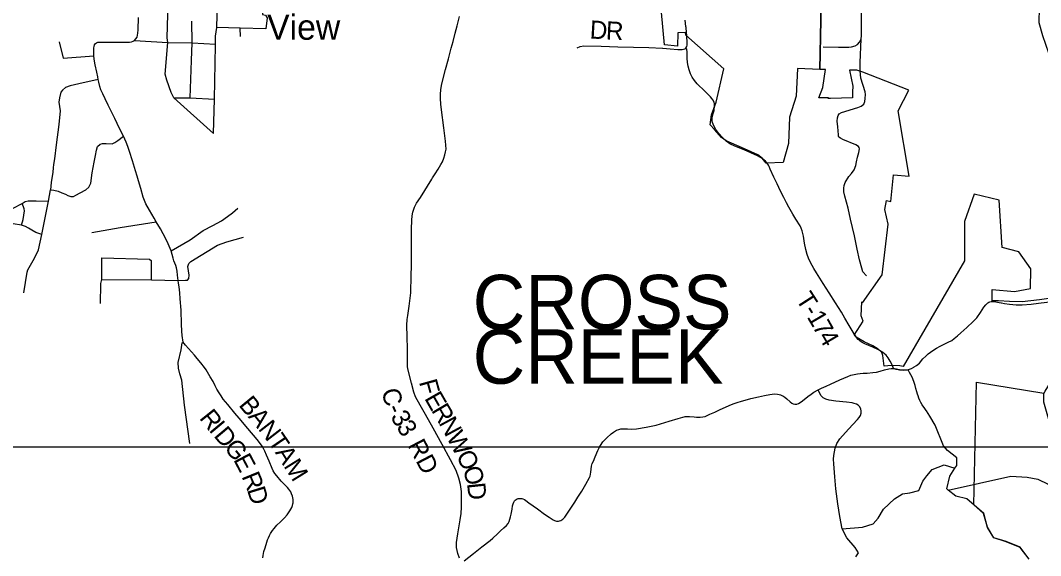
# Model space of a CAD drawing. Extents: x 2402298 to 2498138, y 789485 to 950881.
# Drawn here: x 2459820 to 2476688, y 857480 to 866330 of the extents above; entities that cross this region are included whole.
import ezdxf

# ---------------------------------------------------------------- set-up
doc = ezdxf.new("R2010")
doc.units = 0
for name, color, linetype in [('GM_X_City_Street', 7, 'Continuous'), ('GM_X_Corporation', 7, 'Continuous'), ('GM_X_County_Road', 7, 'Continuous'), ('GM_X_County_Road_Text', 7, 'Continuous'), ('GM_X_Township_Road', 7, 'Continuous'), ('GM_X_Township_Road_Text', 7, 'Continuous'), ('GM_X_Township_Text', 7, 'Continuous'), ('GM_X_Unincorporated_Text', 7, 'Continuous'), ('SH_Text', 7, 'Continuous')]:
    doc.layers.add(name, color=color, linetype=linetype)

msp = doc.modelspace()

# ---------------------------------------------------------------- linework, layer by layer
at = {"layer": 'GM_X_City_Street'}
for points in [[(2473702, 865498), (2473705, 865633), (2473721, 866022), (2473726, 866080), (2473726, 866229), (2473724, 866463), (2473740, 866706), (2473741, 867188), (2473738, 867463), (2473727, 867640), (2473709, 867893), (2473702, 868056), (2473707, 868123), (2473735, 868179), (2473826, 868276), (2473925, 868383), (2474020, 868468), (2474080, 868533), (2474140, 868623), (2474175, 868694), (2474179, 868741), (2474173, 868786)], [(2473095, 865892), (2473349, 865889), (2473471, 865889), (2473520, 865890), (2473560, 865893), (2473623, 865907), (2473663, 865933), (2473691, 865972), (2473721, 866022)]]:
    msp.add_lwpolyline(points, dxfattribs=at)
at = {"layer": 'GM_X_Corporation'}
for points in [[(2473072, 867154), (2473036, 865518), (2472666, 865532), (2472649, 865076), (2472537, 864730), (2472521, 864292), (2472432, 863982), (2472150, 863967), (2472082, 864052), (2472012, 864105), (2471791, 864204), (2471487, 864337), (2471411, 864393), (2471296, 864526), (2471227, 864604), (2471249, 864769), (2471324, 864976), (2471453, 865528), (2470820, 866084), (2470816, 866131), (2470688, 866127), (2470683, 865903), (2470469, 865924), (2470347, 867239)], [(2476971, 861751), (2476668, 861707), (2476385, 861674), (2476175, 861679), (2475993, 861691), (2475889, 861694), (2475889, 861880), (2476256, 861847), (2476522, 861894), (2476528, 862221), (2476330, 862503), (2476052, 862577), (2476001, 863360), (2475589, 863458), (2475428, 863007), (2475428, 862353), (2474418, 860606), (2474359, 860616), (2474225, 860626), (2474100, 860611), (2474080, 860789), (2474061, 860839), (2474005, 860896), (2473915, 860948), (2473772, 861012), (2473703, 861053), (2473638, 861093), (2473606, 861123), (2473752, 861355), (2473722, 861442), (2473730, 861675), (2473743, 861660), (2474066, 862121), (2474170, 862961), (2474115, 863202), (2474139, 863354), (2474209, 863335), (2474258, 863778), (2474515, 863754), (2474332, 864833), (2474512, 865176), (2473748, 865476), (2473652, 865506), (2473531, 865509), (2473582, 865244), (2473576, 865150), (2473579, 865051), (2473214, 865039), (2473198, 865038), (2473175, 865039), (2473179, 865047), (2473022, 865050), (2473090, 865218), (2473129, 865517), (2473036, 865518), (2473072, 867154)], [(2476498, 857423), (2476351, 857617), (2476118, 857713), (2475913, 857775), (2475808, 857950), (2475746, 858177), (2475586, 858319), (2475627, 860345), (2476742, 860163)]]:
    msp.add_lwpolyline(points, dxfattribs=at)
at = {"layer": 'GM_X_County_Road'}
for p, q in [((2474258, 860572), (2474294, 860564)), ((2474294, 860564), (2474303, 860563)), ((2474590, 860597), (2474595, 860600))]:
    msp.add_line(p, q, dxfattribs=at)
for points in [[(2476824, 865786), (2476725, 866075), (2476667, 866287), (2476667, 866397), (2476673, 866484), (2476673, 866612), (2476679, 866737), (2476675, 866808), (2476651, 866875), (2476580, 867029), (2476573, 867046)], [(2462429, 862029), (2462420, 862118), (2462411, 862185), (2462400, 862237), (2462388, 862279), (2462358, 862356), (2462345, 862399), (2462313, 862522), (2462265, 862635), (2462219, 862731), (2462182, 862799), (2462135, 862884), (2462067, 863000), (2462034, 863058), (2461955, 863193), (2461895, 863299), (2461852, 863407), (2461810, 863549), (2461771, 863678), (2461748, 863755), (2461722, 863845), (2461672, 864009), (2461625, 864160), (2461598, 864246), (2461571, 864315), (2461524, 864415), (2461461, 864544), (2461379, 864710), (2461332, 864808), (2461273, 864928), (2461221, 865032), (2461181, 865113), (2461152, 865182), (2461134, 865237), (2461118, 865306), (2461107, 865354), (2461101, 865399), (2461084, 865475), (2461058, 865593), (2461046, 865655), (2461039, 865697), (2461034, 865744), (2461033, 865844), (2461033, 865874), (2461038, 865899), (2461046, 865926), (2461062, 865948), (2461080, 865960), (2461099, 865969), (2461255, 865970), (2461459, 865968), (2461591, 865969), (2461626, 865971), (2461655, 865976), (2461684, 865987), (2461706, 866000), (2461730, 866025), (2461748, 866054), (2461756, 866084), (2461761, 866118), (2461766, 866175), (2461773, 866376)], [(2466634, 863724), (2466678, 863795), (2466725, 863869), (2466772, 863947), (2466797, 863993), (2466821, 864050), (2466838, 864105), (2466850, 864156), (2466857, 864202), (2466855, 864265), (2466846, 864334), (2466820, 864553), (2466783, 864853), (2466771, 864946), (2466765, 865036), (2466765, 865106), (2466773, 865187), (2466788, 865279), (2466851, 865519), (2466898, 865696), (2466943, 865870), (2466973, 865981), (2467010, 866120), (2467041, 866241), (2467082, 866396)], [(2467082, 857435), (2467055, 857512), (2467032, 857612), (2467032, 857694), (2467052, 857842), (2467093, 858071), (2467105, 858174), (2467115, 858279), (2467115, 858413), (2467111, 858540), (2467099, 858653), (2467070, 858762), (2467027, 858886), (2466932, 859063), (2466792, 859319), (2466645, 859589), (2466518, 859811), (2466429, 859966), (2466353, 860103), (2466327, 860183), (2466286, 860331), (2466225, 860569), (2466218, 860608), (2466219, 860668), (2466220, 860900), (2466216, 861095), (2466211, 861291), (2466215, 861382), (2466225, 861450), (2466247, 861606), (2466275, 861825), (2466281, 862114), (2466284, 862274), (2466287, 862582), (2466287, 862759), (2466288, 862876), (2466294, 863026), (2466296, 863098), (2466307, 863159), (2466335, 863244), (2466369, 863307), (2466435, 863404), (2466620, 863702), (2466634, 863724)], [(2462510, 861010), (2462492, 861119), (2462488, 861189), (2462484, 861306), (2462477, 861538), (2462464, 861725), (2462455, 861823), (2462443, 861925), (2462435, 861986), (2462429, 862029)], [(2474595, 860600), (2474634, 860623), (2474684, 860664), (2474743, 860733), (2474788, 860780), (2474830, 860817), (2474908, 860873), (2474966, 860911), (2475026, 860945), (2475157, 861007), (2475218, 861039), (2475261, 861068), (2475315, 861113), (2475368, 861162), (2475469, 861253), (2475575, 861349), (2475635, 861414), (2475695, 861498), (2475749, 861586), (2475782, 861628), (2475813, 861658), (2475833, 861671), (2475851, 861678), (2475873, 861682), (2475893, 861683), (2475947, 861677), (2476002, 861666), (2476034, 861660)], [(2476034, 861660), (2476039, 861659), (2476091, 861649), (2476176, 861635), (2476282, 861626), (2476385, 861627), (2476532, 861639), (2476654, 861653), (2476980, 861692), (2477200, 861722), (2477262, 861726), (2477340, 861721), (2477430, 861709), (2477490, 861700), (2477564, 861687), (2477643, 861674), (2477697, 861665), (2477741, 861661), (2477777, 861662), (2477812, 861676), (2477843, 861697), (2477870, 861719), (2477894, 861754), (2477905, 861772)], [(2463829, 857444), (2463832, 857482), (2463847, 857548), (2463866, 857609), (2463895, 857703), (2463908, 857739), (2463921, 857773), (2463938, 857812), (2463957, 857846), (2463988, 857894), (2464015, 857930), (2464062, 857982), (2464121, 858039), (2464156, 858072), (2464186, 858105), (2464228, 858154), (2464275, 858220), (2464305, 858277), (2464317, 858308), (2464324, 858335), (2464327, 858355), (2464328, 858378), (2464327, 858406), (2464324, 858435), (2464319, 858460), (2464304, 858502), (2464289, 858533), (2464258, 858578), (2464236, 858605), (2464218, 858625), (2464134, 858712), (2464058, 858796), (2464026, 858838), (2463999, 858882), (2463981, 858922), (2463932, 859040), (2463890, 859142), (2463861, 859206), (2463838, 859252), (2463816, 859290), (2463773, 859351), (2463736, 859397), (2463578, 859582), (2463435, 859752), (2463364, 859835), (2463247, 859978), (2463175, 860066), (2463137, 860120), (2463104, 860172), (2463070, 860230), (2463041, 860286), (2463005, 860357), (2462959, 860437), (2462890, 860551), (2462863, 860589), (2462804, 860666), (2462745, 860737), (2462697, 860793), (2462598, 860904), (2462552, 860957), (2462529, 860985), (2462510, 861010)], [(2473009, 860221), (2473063, 860246), (2473142, 860283), (2473216, 860317), (2473370, 860388), (2473503, 860443), (2473552, 860461), (2473603, 860476), (2473662, 860487), (2473706, 860493), (2473755, 860496), (2473822, 860499), (2473915, 860507), (2473977, 860514), (2474034, 860529), (2474109, 860554), (2474178, 860569), (2474216, 860573), (2474258, 860572)], [(2474303, 860563), (2474356, 860553), (2474426, 860547), (2474496, 860553)], [(2474496, 860553), (2474502, 860555), (2474555, 860576), (2474590, 860597)], [(2467156, 857392), (2467310, 857512), (2467451, 857623), (2467585, 857728), (2467632, 857770), (2467706, 857842), (2467759, 857892), (2467815, 857938), (2467856, 857978), (2467883, 858011), (2467899, 858042), (2467914, 858082), (2467925, 858120), (2467936, 858166), (2467948, 858247), (2467957, 858301), (2467965, 858337), (2467977, 858363), (2467991, 858383), (2468003, 858396), (2468017, 858407), (2468032, 858416), (2468051, 858423), (2468071, 858426), (2468091, 858426), (2468109, 858423), (2468128, 858417), (2468153, 858405), (2468176, 858391), (2468227, 858355), (2468367, 858254), (2468487, 858167), (2468560, 858114), (2468594, 858091), (2468631, 858070), (2468650, 858061), (2468668, 858055), (2468685, 858051), (2468701, 858050), (2468718, 858051), (2468734, 858053), (2468756, 858061), (2468773, 858070), (2468789, 858082), (2468804, 858096), (2468822, 858118), (2468845, 858149), (2468986, 858364), (2469038, 858444), (2469102, 858547), (2469168, 858661), (2469229, 858769), (2469238, 858795), (2469245, 858824), (2469250, 858858), (2469264, 858956), (2469276, 859001), (2469293, 859041), (2469325, 859114), (2469368, 859219), (2469393, 859271), (2469409, 859298), (2469450, 859359), (2469514, 859427), (2469586, 859491), (2469626, 859522), (2469678, 859553), (2469713, 859566), (2469750, 859574), (2469805, 859576), (2469858, 859575), (2469926, 859573), (2470007, 859576), (2470168, 859604), (2470330, 859638), (2470544, 859704), (2470695, 859748), (2470770, 859771), (2470793, 859776), (2470813, 859778), (2470845, 859781), (2470881, 859781), (2470959, 859776), (2470997, 859770), (2471058, 859767), (2471105, 859773), (2471140, 859782), (2471219, 859816), (2471303, 859854), (2471390, 859893), (2471478, 859933), (2471541, 859960), (2471607, 859988), (2471670, 860010), (2471744, 860033), (2471804, 860051), (2471895, 860075), (2472024, 860106), (2472121, 860129), (2472211, 860146), (2472247, 860150), (2472290, 860152), (2472337, 860150), (2472363, 860145), (2472385, 860137), (2472407, 860129), (2472425, 860120), (2472460, 860099), (2472493, 860071), (2472547, 860020), (2472573, 860002), (2472596, 859989), (2472625, 859984), (2472655, 859985), (2472684, 859994), (2472728, 860020), (2472779, 860059), (2472840, 860109), (2472895, 860151), (2472938, 860180), (2473009, 860221)]]:
    msp.add_lwpolyline(points, dxfattribs=at)
at = {"layer": 'GM_X_Township_Road'}
for p, q in [((2463459, 866061), (2463453, 866203)), ((2470823, 866231), (2470813, 866334)), ((2461987, 862040), (2461989, 862355)), ((2461145, 861651), (2461150, 861968)), ((2474294, 860564), (2474258, 860572)), ((2474303, 860563), (2474294, 860564))]:
    msp.add_line(p, q, dxfattribs=at)
for points in [[(2463012, 864460), (2462355, 865050), (2462314, 865137), (2462240, 865342), (2462213, 865439), (2462256, 865962), (2462247, 866044), (2462269, 866822), (2462211, 866834), (2462182, 866861), (2462160, 866898), (2462078, 867286), (2462065, 867390), (2462078, 867545)], [(2463047, 865921), (2463047, 865936), (2463045, 866070), (2463067, 866213), (2463079, 866617), (2463064, 866803)], [(2463079, 866617), (2463789, 866598), (2463816, 866576), (2463822, 866430), (2463873, 866414), (2463898, 866374), (2463879, 866191), (2463453, 866203), (2463067, 866213)], [(2462626, 865048), (2462647, 865668), (2462658, 865959), (2462653, 866320)], [(2470832, 866128), (2470825, 866210), (2470823, 866231)], [(2470843, 865920), (2470846, 865954), (2470836, 866081), (2470832, 866128)], [(2460462, 865978), (2460529, 865706), (2461034, 865744)], [(2461706, 866000), (2462256, 865962), (2462658, 865959), (2463047, 865936)], [(2463012, 864460), (2463030, 865027), (2463047, 865921)], [(2469026, 865874), (2469074, 865897), (2469134, 865907), (2469423, 865902), (2469697, 865891), (2469955, 865888), (2470212, 865880), (2470436, 865870), (2470442, 865870)], [(2470442, 865870), (2470562, 865862), (2470691, 865851), (2470698, 865851)], [(2470698, 865851), (2470764, 865850), (2470805, 865859), (2470822, 865869)], [(2471276, 864789), (2471291, 864839), (2471297, 864918), (2471295, 864949), (2471288, 864979), (2471269, 865016), (2471251, 865041), (2471229, 865064), (2471135, 865157), (2471009, 865281), (2470963, 865335), (2470926, 865392), (2470900, 865449), (2470876, 865511), (2470860, 865572), (2470850, 865636), (2470846, 865704), (2470843, 865802), (2470836, 865854), (2470822, 865869), (2470841, 865900), (2470843, 865920)], [(2461107, 865354), (2460784, 865280), (2460640, 865246), (2460567, 865219), (2460514, 865175), (2460488, 865141), (2460465, 865052), (2460457, 864979), (2460475, 864833), (2460455, 864606), (2460410, 864271), (2460384, 864039), (2460369, 863945), (2460363, 863892)], [(2473808, 862106), (2473750, 862171), (2473730, 862231), (2473693, 862368), (2473657, 862546), (2473610, 862769), (2473544, 863043), (2473504, 863224), (2473451, 863422), (2473435, 863493), (2473432, 863556), (2473439, 863600), (2473454, 863652), (2473517, 863747), (2473561, 863799), (2473603, 863860), (2473632, 863932), (2473646, 863992), (2473663, 864068), (2473681, 864145), (2473692, 864208), (2473690, 864228), (2473679, 864245), (2473634, 864275), (2473418, 864362), (2473378, 864384), (2473354, 864398), (2473348, 864418), (2473347, 864440), (2473333, 864568), (2473327, 864665), (2473330, 864718), (2473340, 864758), (2473355, 864783), (2473394, 864809), (2473668, 864892), (2473720, 864914), (2473764, 864944), (2473782, 864988), (2473788, 865037), (2473791, 865103), (2473785, 865150), (2473716, 865373), (2473702, 865498)], [(2462355, 865050), (2462626, 865048), (2463030, 865027)], [(2472188, 863934), (2472168, 863968), (2472140, 864004), (2472083, 864049), (2472006, 864090), (2471787, 864187), (2471632, 864250), (2471550, 864290), (2471488, 864335), (2471429, 864394), (2471368, 864462), (2471319, 864526), (2471281, 864596), (2471260, 864657), (2471258, 864709), (2471265, 864753), (2471276, 864789)], [(2460363, 863892), (2460355, 863819), (2460329, 863647), (2460320, 863526), (2460370, 863520), (2460442, 863508), (2460506, 863481), (2460567, 863458), (2460603, 863433), (2460651, 863419), (2460695, 863419), (2460739, 863441), (2460807, 863481), (2460899, 863526), (2460953, 863572), (2460986, 863636), (2461005, 863811), (2461041, 863984), (2461059, 864094), (2461078, 864186), (2461095, 864245), (2461137, 864283), (2461178, 864294), (2461240, 864295), (2461339, 864291), (2461382, 864310), (2461430, 864345), (2461524, 864415)], [(2473681, 861048), (2473673, 861055), (2473648, 861082), (2473604, 861148), (2473525, 861282), (2473453, 861408), (2473395, 861503), (2473298, 861661), (2473191, 861824), (2473091, 861980), (2473038, 862068), (2472985, 862153), (2472940, 862228), (2472884, 862324), (2472849, 862397), (2472828, 862458), (2472806, 862541), (2472782, 862646), (2472765, 862763), (2472747, 862852), (2472730, 862897), (2472712, 862932), (2472643, 863042), (2472590, 863126), (2472523, 863244), (2472486, 863315), (2472441, 863400), (2472390, 863504), (2472331, 863629), (2472279, 863740), (2472219, 863871), (2472199, 863915), (2472188, 863934)], [(2459876, 861825), (2459930, 862164), (2459943, 862206), (2460051, 862396), (2460121, 862536), (2460173, 862792), (2460285, 863343), (2460320, 863526)], [(2460173, 862792), (2460127, 862807), (2460074, 862823), (2460010, 862860), (2459951, 862893), (2459902, 862920), (2459839, 862945), (2459699, 862964), (2459636, 862981), (2459593, 863007), (2459571, 863032), (2459558, 863061), (2459555, 863096), (2459562, 863123), (2459575, 863145), (2459603, 863173), (2459699, 863226), (2459848, 863302), (2459901, 863335), (2459946, 863346), (2460004, 863348), (2460080, 863349), (2460285, 863343)], [(2459839, 862945), (2459867, 863035), (2459890, 863182), (2459881, 863215), (2459870, 863248), (2459848, 863302)], [(2462313, 862522), (2462626, 862701), (2462843, 862854), (2462999, 862938), (2463144, 863018), (2463246, 863085), (2463326, 863149), (2463417, 863227)], [(2460999, 862821), (2461471, 862907), (2462067, 863000)], [(2462429, 862029), (2462548, 862033), (2462584, 862037), (2462603, 862064), (2462610, 862119), (2462590, 862261), (2462602, 862312), (2462639, 862345), (2463081, 862612), (2463232, 862669), (2463506, 862744)], [(2461150, 861968), (2461150, 861981), (2461166, 862045), (2461165, 862404)], [(2461165, 862404), (2461954, 862381), (2461989, 862355)], [(2461166, 862045), (2461987, 862040), (2462429, 862029)], [(2475162, 858563), (2476197, 858791), (2476468, 858777), (2476640, 858741), (2476811, 858659), (2476976, 858562), (2477141, 858510), (2477122, 858670), (2477110, 858808), (2477069, 858939), (2476998, 859265), (2476836, 859691), (2476786, 859862), (2476744, 860016), (2476743, 860160), (2476766, 860197), (2477153, 860836), (2477274, 861012), (2477352, 861129), (2477397, 861312), (2477403, 861550)], [(2462620, 859336), (2462532, 859966), (2462489, 860379), (2462457, 860485), (2462435, 860580), (2462431, 860674), (2462479, 860884), (2462497, 861000), (2462510, 861010)], [(2474258, 860572), (2474232, 860633), (2474202, 860697), (2474168, 860751), (2474132, 860793), (2474078, 860837), (2474007, 860881), (2473913, 860925), (2473781, 860982), (2473739, 861004), (2473704, 861028), (2473681, 861048)], [(2474496, 860553), (2474426, 860547), (2474356, 860553), (2474303, 860563)], [(2474653, 860151), (2474643, 860187), (2474627, 860244), (2474613, 860293), (2474593, 860359), (2474565, 860429), (2474522, 860505), (2474496, 860553)], [(2473632, 857459), (2473677, 857526), (2473624, 857614), (2473486, 857773), (2473408, 857925), (2473366, 858128), (2473333, 858338), (2473305, 858586), (2473287, 858784), (2473270, 858995), (2473266, 859073), (2473269, 859136), (2473289, 859256), (2473320, 859336), (2473367, 859413), (2473511, 859572), (2473660, 859728), (2473688, 859761), (2473708, 859796), (2473719, 859835), (2473723, 859867), (2473714, 859909), (2473695, 859943), (2473672, 859965), (2473643, 859983), (2473608, 859997), (2473570, 860006), (2473481, 860019), (2473300, 860033), (2473191, 860051), (2473137, 860067), (2473092, 860090), (2473060, 860121), (2473038, 860159), (2473009, 860221)], [(2474798, 859878), (2474775, 859913), (2474732, 859971), (2474709, 860009), (2474692, 860045), (2474674, 860084), (2474661, 860123), (2474653, 860151)], [(2476500, 857420), (2476352, 857614), (2476119, 857710), (2475914, 857772), (2475809, 857947), (2475747, 858174), (2475469, 858420), (2475285, 858463), (2475162, 858563), (2475137, 858584), (2475185, 858794), (2475272, 858925), (2475302, 858970), (2475301, 859096), (2475147, 859218), (2475080, 859297), (2474947, 859638), (2474855, 859788), (2474800, 859876), (2474798, 859878)], [(2473408, 857925), (2473746, 857950), (2473919, 858004), (2474001, 858097), (2474093, 858245), (2474272, 858417), (2474402, 858503), (2474524, 858519), (2474673, 858557), (2474741, 858708), (2474805, 858799), (2474896, 858903), (2475092, 858982), (2475272, 858925)]]:
    msp.add_lwpolyline(points, dxfattribs=at)
at = {"layer": 'SH_Text'}
msp.add_lwpolyline([(2448187, 889729), (2496836, 889729), (2496836, 859271), (2448187, 859271)], close=True, dxfattribs=at)

# ---------------------------------------------------------------- texts
at = {"layer": 'GM_X_County_Road_Text'}
for s, rotation, p in [('F', 285.4677, (2466408, 860352)), ('B', 309.4523, (2463418, 859966)), ('C', 284.9573, (2465787, 860205)), ('E', 299.7819, (2466493, 860082)), ('-', 294.2788, (2465868, 859917)), ('R', 300.5843, (2466607, 859883)), ('R', 308.5836, (2462767, 859751)), ('A', 309.4404, (2463575, 859775)), ('3', 299.2998, (2465932, 859779)), ('N', 298.4078, (2466731, 859674)), ('I', 309.9485, (2462925, 859553)), ('D', 310.0376, (2463005, 859458)), ('N', 307.8178, (2463741, 859573)), ('3', 301.1707, (2466028, 859609)), ('T', 304.2428, (2463900, 859369)), ('W', 297.6985, (2466856, 859442)), ('G', 309.9007, (2463174, 859256)), ('RD', 297.667, (2466215, 859307)), ('E', 297.8416, (2463335, 859067)), ('A', 301.9915, (2464024, 859186)), ('O', 296.5325, (2467017, 859136)), ('M', 301.8376, (2464164, 858962)), ('O', 286.8912, (2467130, 858912)), ('R', 292.2515, (2463473, 858791)), ('D', 287.215, (2463564, 858570)), ('D', 275.9448, (2467204, 858674))]:
    msp.add_text(s, height=300, rotation=rotation, dxfattribs=at).set_placement(p)
at = {"layer": 'GM_X_Township_Road_Text'}
for s, rotation, p in [('D', 356.6395, (2469228, 866032)), ('R', 357.4514, (2469496, 866016)), ('T', 302.6, (2472632, 861719)), ('1', 300.3801, (2472817, 861428)), ('-', 301.9665, (2472753, 861530)), ('7', 299.1259, (2472909, 861270)), ('4', 300.4492, (2473003, 861102))]:
    msp.add_text(s, height=300, rotation=rotation, dxfattribs=at).set_placement(p)
at = {"layer": 'GM_X_Township_Text'}
for s, p in [('CROSS', (2467298, 861222)), ('CREEK', (2467298, 860322))]:
    msp.add_text(s, height=900, rotation=0, dxfattribs=at).set_placement(p)
at = {"layer": 'GM_X_Unincorporated_Text'}
msp.add_text('View', height=417, rotation=0, dxfattribs=at).set_placement((2463899, 866010))

doc.saveas('drawing.dxf')
